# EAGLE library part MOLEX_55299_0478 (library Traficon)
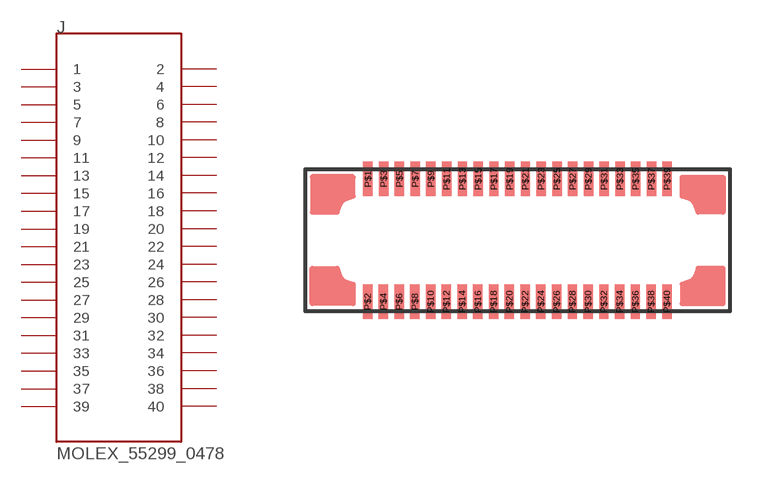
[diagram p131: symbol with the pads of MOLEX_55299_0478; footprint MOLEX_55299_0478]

Designator prefix J

## MOLEX_55299_0478  [MOLEX_55299_0478]
P$1  1
P$2  2
P$3  3
P$4  4
P$5  5
P$6  6
P$7  7
P$8  8
P$9  9
P$10  10
P$11  11
P$12  12
P$13  13
P$14  14
P$15  15
P$16  16
P$17  17
P$18  18
P$19  19
P$20  20
P$21  21
P$22  22
P$23  23
P$24  24
P$25  25
P$26  26
P$27  27
P$28  28
P$29  29
P$30  30
P$31  31
P$32  32
P$33  33
P$34  34
P$35  35
P$36  36
P$37  37
P$38  38
P$39  39
P$40  40

## Footprint MOLEX_55299_0478 (pad centres in mm)
smd 0.3 x 1.1: P$1 -4.754,1.95; P$2 -4.763,-1.952; P$3 -4.254,1.95; P$4 -4.263,-1.952; P$5 -3.754,1.95; P$6 -3.763,-1.952; P$7 -3.254,1.95; P$8 -3.263,-1.952; P$9 -2.754,1.95; P$10 -2.763,-1.952; P$11 -2.254,1.95; P$12 -2.263,-1.952; P$13 -1.754,1.95; P$14 -1.763,-1.952; P$15 -1.254,1.95; P$16 -1.263,-1.952; P$17 -0.754,1.95; P$18 -0.763,-1.952; P$19 -0.254,1.95; P$20 -0.263,-1.952; P$21 0.246,1.95; P$22 0.237,-1.952; P$23 0.746,1.95; P$24 0.737,-1.952; P$25 1.246,1.95; P$26 1.237,-1.952; P$27 1.746,1.95; P$28 1.737,-1.952; P$29 2.246,1.95; P$30 2.237,-1.952; P$31 2.746,1.95; P$32 2.737,-1.952; P$33 3.246,1.95; P$34 3.237,-1.952; P$35 3.746,1.95; P$36 3.737,-1.952; P$37 4.246,1.95; P$38 4.237,-1.952; P$39 4.746,1.95; P$40 4.737,-1.952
